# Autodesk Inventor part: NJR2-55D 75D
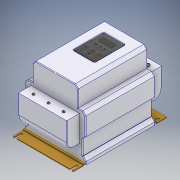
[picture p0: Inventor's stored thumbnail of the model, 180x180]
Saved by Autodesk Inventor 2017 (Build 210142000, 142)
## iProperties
Part Number: NJR2-55D 75D
Material: Типовые
Document SubType Name: Modeling
Designer: RSagdiev
Density: 1 g/cm^3
Appearance: По умолчанию
Author: RSagdiev
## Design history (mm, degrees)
sketch "Эскиз1"
  geometry: L1 (0, 0)-(14.471, 0) reference; L2 (0, 0)-(0, 21.118) reference; L3 (0, 0)-(230, 0); L4 (230, 0)-(230, 20); L5 (230, 215)-(0, 215); L6 (0, 215)-(0, 150); L7 (230, 20)-(0, 20); L8 (230, 70)-(0, 70); L9 (230, 70)-(230, 150); L10 (230, 20)-(230, 70); L11 (0, 70)-(0, 20); L12 (0, 20)-(0, 0); L13 (230, 150)-(0, 150); L14 (230, 150)-(230, 215); L15 (0, 150)-(0, 70)
  constraints: 30 end point, 17 parallel, 14 perpendicular, 3 horizontal, 2 vertical, 1 point on line
  dimensions: "d0" = 230 distance of L5.end L5.start; "d1" = 215 distance of L5.start L3.end; "d2" = 20 distance between parallel lines of L3 L7; "d3" = 50 distance between parallel lines of L8 L7; "d4" = 80 distance between parallel lines of L13 L8
extrude "Выдавливание1" new body sketch "Эскиз1" stored distance "d5" = 202; taper "d6" = 0 deg
extrude "Выдавливание2" join sketch "Эскиз1" stored distance "d7" = 180; taper "d8" = 0 deg
extrude "Выдавливание3" join sketch "Эскиз1" stored distance "d9" = 200; taper "d10" = 0 deg
extrude "Выдавливание4" join sketch "Эскиз1" stored distance "d11" = 150; taper "d12" = 0 deg
chamfer "Фаска1" distance "d13" = 10; stored, may be unused: second distance "d14" = 2, angle "d15" = 45 deg
sketch "Эскиз2"
  geometry: L1 (270, 0)-(236, 0); L2 (235, 1)-(235, 3); L3 (234, 4)-(-4, 4); L4 (-5, 3)-(-5, 1); L5 (-6, 0)-(-40, 0); L6 (230, 10)-(230, 0) reference; L7 (230, 0)-(0, 0) reference; L8 (0, 0)-(0, 10) reference; L9 (270, 3)-(238, 3); L10 (234, 7)-(-4, 7); L11 (-8, 3)-(-40, 3); L12 (-40, 0)-(-40, 3); L13 (270, 3)-(270, 0); A1 r 1 centre (-6, 1) between (-6, 0) and (-5, 1); A2 r 1 centre (-4, 3) between (-4, 4) and (-5, 3); A3 r 1 centre (236, 1) between (235, 1) and (236, 0); A4 r 1 centre (234, 3) between (235, 3) and (234, 4); A5 r 4 centre (234, 3) between (238, 3) and (234, 7); A6 r 4 centre (-4, 3) between (-4, 7) and (-8, 3); 4 further points
  constraints: 20 end point, 12 point on circle, 10 point on line, 8 tangent, 6 centre point, 4 perpendicular, 3 equal radius, 1 horizontal, 1 parallel, 4 other
  dimensions: "d16" = 4 distance of point (235, 0) point (235, 4); "d17" = 5 distance between parallel lines of L2 L6; "d18" = 4 distance between parallel lines of L7 L3; "d19" = 35 distance of point (235, 0) L1.start; "d20" = 35 distance of point (-5, 0) L5.end (= d19); "d21" = 4 distance of point (-5, 4) point (-5, 0) (derived); "d22" = 5 distance between parallel lines of L4 L8 (= d17); "d23" = 310 distance of L5.end L1.start (derived); "d24" = 1 radius of A1; "d25" = 3 distance between parallel lines of L1 L9
extrude "Выдавливание5" new body sketch "Эскиз2" stored distance "d26" = 200; taper "d27" = 0 deg
sketch "Эскиз4"
  geometry: L1 (272.5, 138)-(-42.5, 138); L2 (-42.5, 138)-(-42.5, 50); L3 (-42.5, 50)-(272.5, 50); L4 (272.5, 50)-(272.5, 138); L5 (230, 150)-(230, 205) reference; L6 (230, 150)-(0, 150) reference; L7 (230, 70)-(0, 70) reference; 1 further point
  constraints: 8 end point, 2 parallel, 1 horizontal, 1 perpendicular
  dimensions: "d28" = 315 distance between parallel lines of L2 L4; "d29" = 42.5 distance between parallel lines of L4 L5 (= -0.5 x d0 + 0.5 x d28); "d31" = 20 distance between parallel lines of L7 L3; "d34" = 12 distance between parallel lines of L1 L6
extrude "Выдавливание6" join sketch "Эскиз4" stored distance "d32" = 160; taper "d33" = 0 deg
fillet "Сопряжение1" dims "d35" = 25
sketch "Эскиз5" dims "d44" = 10
  geometry: L1 (160, 0)-(0, 0) reference; L2 (160, 42.5)-(160, 0) reference; L3 (160, 42.5)-(0, 42.5) reference; L4 (0, 0)-(0, 42.5) reference; C1 r 4 at (20, 20); C2 r 4 at (43.333, 20); C3 r 4 at (66.667, 20); C4 r 4 at (90, 20); C5 r 4 at (113.333, 20); C6 r 4 at (136.667, 20); 1 further point
  constraints: 6 centre point, 1 horizontal, 10 other
  dimensions: "d36" = 8 diameter of C1; "d37" = 160 distance between parallel lines of L2 L4 (derived); "d38" = 20 distance from line of C1.centre L4; "d41" = 23.33333 distance of C1.centre C2.centre (= -0.166667 x d38 + 0.166667 x d37)
  node "Спроецированная петля1"
extrude "Выдавливание7" cut sketch "Эскиз5" distance "d46" = 20; taper "d47" = 0 deg
extrude "Выдавливание8" new body sketch "Эскиз5" distance "d48" = 20; taper "d49" = 0 deg
sketch "Эскиз6" dims "d50" = 12, "d56" = 10
  geometry: L1 (0, 6)-(5.196, 3); L2 (5.196, 3)-(5.196, -3); L3 (5.196, -3)-(0, -6); L4 (0, -6)-(-5.196, -3); L5 (-5.196, -3)-(-5.196, 3); L6 (-5.196, 3)-(0, 6); L7 (140, 22.5)-(-20, 22.5) reference; L8 (23.333, 6)-(28.529, 3); L9 (28.529, 3)-(28.529, -3); L10 (28.529, -3)-(23.333, -6); L11 (23.333, -6)-(18.137, -3); L12 (18.137, -3)-(18.137, 3); L13 (18.137, 3)-(23.333, 6); L14 (46.667, 6)-(51.863, 3); L15 (51.863, 3)-(51.863, -3); L16 (51.863, -3)-(46.667, -6); L17 (46.667, -6)-(41.471, -3); L18 (41.471, -3)-(41.471, 3); L19 (41.471, 3)-(46.667, 6); L20 (70, 6)-(75.196, 3); L21 (75.196, 3)-(75.196, -3); L22 (75.196, -3)-(70, -6); L23 (70, -6)-(64.804, -3); L24 (64.804, -3)-(64.804, 3); L25 (64.804, 3)-(70, 6); L26 (93.333, 6)-(98.529, 3); L27 (98.529, 3)-(98.529, -3); L28 (98.529, -3)-(93.333, -6); L29 (93.333, -6)-(88.137, -3); L30 (88.137, -3)-(88.137, 3); L31 (88.137, 3)-(93.333, 6); L32 (116.667, 6)-(121.863, 3); L33 (121.863, 3)-(121.863, -3); L34 (121.863, -3)-(116.667, -6); L35 (116.667, -6)-(111.471, -3); L36 (111.471, -3)-(111.471, 3); L37 (111.471, 3)-(116.667, 6); 13 further points
  constraints: 72 end point, 6 coincident, 6 horizontal, 6 vertical alignment, 95 other
  dimensions: "d53" = 23.33333 distance of point (0, 0) point (23.333, 0) (= -0.166667 x d38 + 0.166667 x d37)
extrude "Выдавливание9" join sketch "Эскиз6" distance "d58" = 5; taper "d59" = 0 deg
sketch "Эскиз7"
  geometry: L1 (5.196, 3)-(0, 6) reference; L2 (0, 6)-(-5.196, 3) reference; L3 (-5.196, 3)-(-5.196, -3) reference; L4 (-5.196, -3)-(0, -6) reference; L5 (0, -6)-(5.196, -3) reference; L6 (5.196, -3)-(5.196, 3) reference; L7 (0, 3.691)-(3.196, 1.845); L8 (3.196, 1.845)-(3.196, -1.845); L9 (3.196, -1.845)-(0, -3.691); L10 (0, -3.691)-(-3.196, -1.845); L11 (-3.196, -1.845)-(-3.196, 1.845); L12 (-3.196, 1.845)-(0, 3.691); L13 (28.529, 3)-(23.333, 6) reference; L14 (23.333, 6)-(18.137, 3) reference; L15 (18.137, 3)-(18.137, -3) reference; L16 (18.137, -3)-(23.333, -6) reference; L17 (23.333, -6)-(28.529, -3) reference; L18 (28.529, -3)-(28.529, 3) reference; L19 (51.863, 3)-(46.667, 6) reference; L20 (46.667, 6)-(41.471, 3) reference; L21 (41.471, 3)-(41.471, -3) reference; L22 (41.471, -3)-(46.667, -6) reference; L23 (46.667, -6)-(51.863, -3) reference; L24 (51.863, -3)-(51.863, 3) reference; L25 (75.196, 3)-(70, 6) reference; L26 (70, 6)-(64.804, 3) reference; L27 (64.804, 3)-(64.804, -3) reference; L28 (64.804, -3)-(70, -6) reference; L29 (70, -6)-(75.196, -3) reference; L30 (75.196, -3)-(75.196, 3) reference; L31 (98.529, 3)-(93.333, 6) reference; L32 (93.333, 6)-(88.137, 3) reference; L33 (88.137, 3)-(88.137, -3) reference; L34 (88.137, -3)-(93.333, -6) reference; L35 (93.333, -6)-(98.529, -3) reference; L36 (98.529, -3)-(98.529, 3) reference; L37 (121.863, 3)-(116.667, 6) reference; L38 (116.667, 6)-(111.471, 3) reference; L39 (111.471, 3)-(111.471, -3) reference; L40 (111.471, -3)-(116.667, -6) reference; L41 (116.667, -6)-(121.863, -3) reference; L42 (121.863, -3)-(121.863, 3) reference; L43 (23.333, 3.691)-(26.529, 1.845); L44 (26.529, 1.845)-(26.529, -1.845); L45 (26.529, -1.845)-(23.333, -3.691); L46 (23.333, -3.691)-(20.137, -1.845); L47 (20.137, -1.845)-(20.137, 1.845); L48 (20.137, 1.845)-(23.333, 3.691); L49 (43.471, 1.845)-(46.667, 3.691); L50 (46.667, 3.691)-(49.863, 1.845); L51 (49.863, 1.845)-(49.863, -1.845); L52 (49.863, -1.845)-(46.667, -3.691); L53 (46.667, -3.691)-(43.471, -1.845); L54 (43.471, -1.845)-(43.471, 1.845); L55 (66.804, 1.845)-(70, 3.691); L56 (70, 3.691)-(73.196, 1.845); L57 (73.196, 1.845)-(73.196, -1.845); L58 (73.196, -1.845)-(70, -3.691); L59 (70, -3.691)-(66.804, -1.845); L60 (66.804, -1.845)-(66.804, 1.845); L61 (90.137, 1.845)-(93.333, 3.691); L62 (93.333, 3.691)-(96.529, 1.845); L63 (96.529, 1.845)-(96.529, -1.845); L64 (96.529, -1.845)-(93.333, -3.691)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; 1 further point
  constraints: 72 end point, 30 other
  dimensions: "d60" = 2 distance between parallel lines of L1 L7; "d61" = 2 distance between parallel lines of L13 L43; "d62" = 2 distance between parallel lines of L20 L49; "d63" = 2 distance between parallel lines of L26 L55; "d64" = 2 distance between parallel lines of L32 L61; "d65" = 2 distance between parallel lines of L38 L67
extrude "Выдавливание10" cut sketch "Эскиз7" distance "d66" = 1.5; taper "d67" = 0 deg
fillet "Сопряжение2" dims "d68" = 2
sketch "Эскиз8"
  geometry: L1 (0, -310)-(200, -310) reference; L2 (200, 0)-(0, 0) reference; L3 (200, 0)-(200, -34) reference; L4 (0, -34)-(0, 0) reference; L5 (8.5, -20)-(8.5, -25); L6 (191.5, -20)-(191.5, -25); L7 (8.5, -20)-(191.5, -20); L8 (8.5, -290)-(8.5, -310); L9 (5, -290)-(5, -310); L10 (12, -310)-(12, -290); L11 (8.5, -20)-(8.5, -290); L12 (8.5, -290)-(191.5, -290); L13 (191.5, -20)-(191.5, -290); L14 (191.5, -290)-(191.5, -310); L15 (188, -290)-(188, -310); L16 (195, -310)-(195, -290); A1 r 3.5 centre (8.5, -20) between (11.779, -21.225) and (5.221, -21.225); A2 r 5 centre (8.5, -25) between (5.221, -21.225) and (11.779, -21.225); A3 r 3.5 centre (191.5, -20) between (194.779, -21.225) and (188.221, -21.225); A4 r 5 centre (191.5, -25) between (188.221, -21.225) and (194.779, -21.225); A5 r 3.5 centre (8.5, -290) between (12, -290) and (5, -290); A6 r 3.5 centre (8.5, -310) between (5, -310) and (12, -310); A7 r 3.5 centre (191.5, -290) between (195, -290) and (188, -290); A8 r 3.5 centre (191.5, -310) between (188, -310) and (195, -310); 5 further points
  constraints: 28 end point, 16 point on circle, 8 centre point, 8 tangent, 4 vertical, 3 coincident, 2 horizontal, 2 midpoint, 2 parallel, 2 perpendicular, 2 point on line
  dimensions: "d69" = 183 distance of point (191.5, -20) point (8.5, -20); "d70" = 270 distance of L8.start point (8.5, -20); "d71" = 310 distance between parallel lines of L1 L2 (derived); "d72" = 20 distance from line of L2 point (8.5, -20) (= -0.5 x d70 + 0.5 x d71); "d73" = 200 distance between parallel lines of L3 L4 (derived); "d74" = 8.5 distance from line of L4 point (8.5, -20) (= -0.5 x d69 + 0.5 x d73); "d75" = 7 diameter of A1; "d76" = 10 diameter of A2; "d77" = 5 distance of L5.start L5.end; "d78" = 7 diameter of A3; "d79" = 10 diameter of A4; "d80" = 5 distance of L6.start L6.end; "d81" = 7 diameter of A6; "d82" = 7 diameter of A8
extrude "Выдавливание11" cut sketch "Эскиз8" distance "d83" = 5.5; taper "d84" = 0 deg
fillet "Сопряжение3" dims "d85" = 2
sketch "Эскиз9"
  geometry: L1 (130, 0)-(0, 0) reference; L2 (130, 226)-(130, 0) reference; L3 (0, 226)-(130, 226) reference; L4 (0, 0)-(0, 226) reference; L5 (33, 193)-(97, 193); L6 (100, 190)-(100, 96); L7 (97, 93)-(33, 93); L8 (30, 96)-(30, 190); L9 (97, 195)-(33, 195); L10 (28, 190)-(28, 96); L11 (33, 91)-(97, 91); L12 (102, 96)-(102, 190); A1 r 3 centre (33, 190) between (33, 193) and (30, 190); A2 r 3 centre (97, 190) between (100, 190) and (97, 193); A3 r 3 centre (97, 96) between (97, 93) and (100, 96); A4 r 3 centre (33, 96) between (30, 96) and (33, 93); A5 r 5 centre (33, 190) between (33, 195) and (28, 190); A6 r 5 centre (33, 96) between (28, 96) and (33, 91); A7 r 5 centre (97, 96) between (97, 91) and (102, 96); A8 r 5 centre (97, 190) between (102, 190) and (97, 195); 4 further points
  constraints: 16 end point, 16 point on circle, 8 centre point, 8 tangent, 6 point on line, 4 parallel, 3 equal radius, 2 perpendicular, 1 horizontal, 7 other
  dimensions: "d86" = 70 distance of point (100, 93) point (30, 93); "d87" = 100 distance of point (100, 193) point (100, 93); "d88" = 130 distance of L3.start L2.start (derived); "d89" = 226 distance of L1.end L3.start (derived); "d90" = 33 distance between parallel lines of L3 L5 (computed from d89, d87); "d91" = 30 distance between parallel lines of L4 L8 (= -0.5 x d86 + 0.5 x d88); "d92" = 3 radius of A1; "d93" = 2 distance between parallel lines of L5 L9
  node "Спроецированная петля8"
extrude "Выдавливание12" cut sketch "Эскиз9" distance "d94" = 25; taper "d95" = 0 deg
extrude "Выдавливание13" new body sketch "Эскиз9" distance "d96" = 25; taper "d97" = 0 deg
sketch "Эскиз10"
  geometry: L1 (30, 190)-(30, 150.574); L2 (33, 93)-(97, 93); L3 (100, 96)-(100, 150.574); L4 (97, 193)-(33, 193); L5 (97, 193)-(33, 193) reference; L6 (30, 190)-(30, 96) reference; L7 (30, 150.574)-(30, 96); L8 (100, 150.574)-(100, 190); L9 (45.628, 161.287)-(84.628, 161.287); L10 (87.628, 164.287)-(87.628, 176.287); L11 (84.628, 179.287)-(45.628, 179.287); L12 (42.628, 176.287)-(42.628, 164.287); L13 (42.628, 161.287)-(87.628, 179.287); L14 (87.628, 161.287)-(42.628, 179.287); A1 r 3 centre (33, 96) between (30, 96) and (33, 93); A2 r 3 centre (97, 96) between (97, 93) and (100, 96); A3 r 3 centre (97, 190) between (100, 190) and (97, 193); A4 r 3 centre (33, 190) between (33, 193) and (30, 190); A5 r 55 centre (65, 193) between (30, 150.574) and (100.197, 150.737); A6 r 3 centre (45.628, 176.287) between (45.628, 179.287) and (42.628, 176.287); A7 r 3 centre (45.628, 164.287) between (42.628, 164.287) and (45.628, 161.287); A8 r 3 centre (84.628, 176.287) between (87.628, 176.287) and (84.628, 179.287); A9 r 3 centre (84.628, 164.287) between (84.628, 161.287) and (87.628, 164.287); 2 further points
  constraints: 20 end point, 11 point on circle, 9 centre point, 9 point on line, 8 tangent, 3 equal radius, 3 midpoint, 2 parallel, 1 horizontal, 1 perpendicular
  dimensions: "d98" = 55 radius of A5; "d99" = 45 distance of L14.end L13.end; "d100" = 18 distance of L13.end L14.start; "d101" = 22.7132 distance from line of L4 point (65.128, 170.287); "d102" = 35.1281 distance from line of L1 point (65.128, 170.287); "d103" = 3 radius of A6 (derived)
extrude "Выдавливание14" cut sketch "Эскиз10" distance "d104" = 1; taper "d105" = 0 deg
sketch "Эскиз11"
  geometry: L1 (30, 150.574)-(30, 96) reference; L2 (33, 93)-(97, 93) reference; L3 (100, 96)-(100, 150.574) reference; L4 (30, 150.574)-(30, 96) reference; L5 (30, 123)-(100, 123); L6 (100, 96)-(100, 150.574) reference; L7 (30, 108)-(100, 108); L8 (33, 93)-(97, 93) reference; L9 (41.667, 93)-(41.667, 143.195); L10 (88.333, 93)-(88.333, 143.195); L11 (65, 93)-(65, 138); L12 (36.667, 128)-(46.667, 128); L13 (46.667, 128)-(46.667, 118); L14 (46.667, 118)-(36.667, 118); L15 (36.667, 118)-(36.667, 128); L16 (36.667, 128)-(46.667, 118); L17 (46.667, 128)-(36.667, 118); L18 (36.667, 113)-(46.667, 113); L19 (46.667, 113)-(46.667, 103); L20 (46.667, 103)-(36.667, 103); L21 (36.667, 103)-(36.667, 113); L22 (36.667, 113)-(46.667, 103); L23 (46.667, 113)-(36.667, 103); L24 (60, 128)-(70, 128); L25 (70, 128)-(70, 118); L26 (70, 118)-(60, 118); L27 (60, 118)-(60, 128); L28 (60, 128)-(70, 118); L29 (70, 128)-(60, 118); L30 (60, 113)-(70, 113); L31 (70, 113)-(70, 103); L32 (70, 103)-(60, 103); L33 (60, 103)-(60, 113); L34 (60, 113)-(70, 103); L35 (70, 113)-(60, 103); L36 (83.333, 128)-(93.333, 128); L37 (93.333, 128)-(93.333, 118); L38 (93.333, 118)-(83.333, 118); L39 (83.333, 118)-(83.333, 128); L40 (83.333, 128)-(93.333, 118); L41 (93.333, 128)-(83.333, 118); L42 (83.333, 113)-(93.333, 113); L43 (93.333, 113)-(93.333, 103); L44 (93.333, 103)-(83.333, 103); L45 (83.333, 103)-(83.333, 113); L46 (83.333, 113)-(93.333, 103); L47 (93.333, 113)-(83.333, 103); L48 (46.767, 128.1)-(36.567, 128.1); L49 (36.567, 128.1)-(36.567, 117.9); L50 (36.567, 117.9)-(46.767, 117.9); L51 (46.767, 117.9)-(46.767, 128.1); L52 (70.1, 128.1)-(59.9, 128.1); L53 (59.9, 128.1)-(59.9, 117.9); L54 (59.9, 117.9)-(70.1, 117.9); L55 (70.1, 117.9)-(70.1, 128.1); L56 (93.433, 128.1)-(83.233, 128.1); L57 (83.233, 128.1)-(83.233, 117.9); L58 (83.233, 117.9)-(93.433, 117.9); L59 (93.433, 117.9)-(93.433, 128.1); L60 (46.767, 113.1)-(36.567, 113.1); L61 (36.567, 113.1)-(36.567, 102.9); L62 (36.567, 102.9)-(46.767, 102.9); L63 (46.767, 102.9)-(46.767, 113.1); L64 (70.1, 113.1)-(59.9, 113.1)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; A1 r 55 centre (65, 193) between (30, 150.574) and (100, 150.574) reference; A2 r 3 centre (33, 96) between (30, 96) and (33, 93) reference; A3 r 3 centre (97, 96) between (97, 93) and (100, 96) reference; A4 r 55 centre (65, 193) between (30, 150.574) and (100, 150.574) reference; 8 further points
  constraints: 130 end point, 24 parallel, 16 midpoint, 16 point on line, 14 perpendicular, 7 horizontal, 4 point on circle, 1 vertical, 18 other
  dimensions: "d106" = 70 distance between parallel lines of L3 L1 (derived); "d107" = 45 distance from line of L2 L11.end (derived); "d108" = 15 distance between parallel lines of L7 L5 (= 0.333333 x d107); "d109" = 15 distance from line of L11.end L5 (= 0.333333 x d107); "d110" = 23.33333 distance between parallel lines of L11 L10 (= 0.333333 x d106); "d111" = 23.33333 distance between parallel lines of L11 L9 (= d110); "d112" = 10 distance of L13.end L14.end; "d113" = 10 distance of L12.end L13.end; "d114" = 10 distance of L19.end L20.end; "d115" = 10 distance of L18.end L19.end; "d116" = 10 distance of L25.end L26.end; "d117" = 10 distance of L24.end L25.end; "d118" = 10 distance of L31.end L32.end; "d119" = 10 distance of L30.end L31.end; "d120" = 10 distance of L37.end L38.end; "d121" = 10 distance of L36.end L37.end; "d122" = 10 distance of L43.end L44.end; "d123" = 10 distance of L42.end L43.end; "d124" = 0.1 distance between parallel lines of L12 L48; "d125" = 0.1 distance between parallel lines of L24 L52; "d126" = 0.1 distance between parallel lines of L36 L56; "d127" = 0.1 distance between parallel lines of L18 L60; "d128" = 0.1 distance between parallel lines of L30 L64; "d129" = 0.1 distance between parallel lines of L42 L68
extrude "Выдавливание15" cut sketch "Эскиз11" distance "d130" = 3; taper "d131" = 0 deg
sketch "Эскиз12"
  geometry: L1 (100, 96)-(100, 150.574) reference; L2 (50, 144.701)-(80, 144.701); C1 r 1.5 at (65, 144.701); C2 r 1.5 at (80, 144.701); C3 r 1.5 at (50, 144.701); C4 r 1.6 at (50, 144.701); C5 r 1.6 at (65, 144.701); C6 r 1.6 at (80, 144.701); A1 r 55 centre (65, 193) between (30, 150.574) and (100, 150.574) reference; 1 further point
  constraints: 6 centre point, 2 end point, 1 coincident, 1 horizontal, 1 midpoint
  dimensions: "d132" = 3 diameter of C1; "d133" = 3 diameter of C2; "d134" = 3 diameter of C3; "d135" = 48.29941 distance of A1.centre C1.centre; "d136" = 35 distance from line of L1 C1.centre; "d137" = 15 distance of C1.centre C2.centre; "d138" = 15 distance of C1.centre L2.start; "d139" = 0.1 radial gap between concentric circles of C3 C4; "d140" = 0.1 radial gap between concentric circles of C1 C5; "d141" = 0.1 radial gap between concentric circles of C2 C6
extrude "Выдавливание16" cut sketch "Эскиз12" distance "d142" = 3; taper "d143" = 0 deg
sketch "Эскиз13"
  geometry: L1 (45, 150.348)-(102.075, 150.348); L2 (102.075, 150.348)-(102.075, 146.701); L3 (102.075, 146.701)-(45, 146.701); L4 (45, 146.701)-(45, 150.348); C1 r 1.5 at (50, 144.701) reference; 1 further point
  constraints: 2 other
  dimensions: "d144" = 2 vertical distance of L3.end C1.centre; "d145" = 5 horizontal distance of C1.centre L3.end
feature "Рельеф1" sketch "Эскиз13" dims "d146" = 0.1, "d147" = 0
sketch "Эскиз14"
  geometry: L1 (36.734, 124.406)-(51.145, 124.406); L2 (51.145, 124.406)-(51.145, 120.906); L3 (51.145, 120.906)-(36.734, 120.906); L4 (36.734, 120.906)-(36.734, 124.406); L5 (38.873, 106.059)-(38.873, 109.559); L6 (38.873, 109.559)-(53.285, 109.559); L7 (53.285, 109.559)-(53.285, 106.059); L8 (53.285, 106.059)-(38.873, 106.059); L9 (84.699, 105.985)-(84.699, 109.485); L10 (84.699, 109.485)-(99.11, 109.485); L11 (99.11, 109.485)-(99.11, 105.985); L12 (99.11, 105.985)-(84.699, 105.985); L13 (85.21, 120.906)-(85.21, 124.406); L14 (85.21, 124.406)-(99.621, 124.406); L15 (99.621, 124.406)-(99.621, 120.906); L16 (99.621, 120.906)-(85.21, 120.906); 1 further point
  constraints: 8 other
feature "Рельеф2" dims "d148" = 0.1, "d149" = 0
feature "Рельеф3" dims "d150" = 0.1, "d151" = 0
feature "Рельеф4" dims "d152" = 0.1, "d153" = 0
feature "Рельеф5" dims "d154" = 0.1, "d155" = 0
sketch "Эскиз15" dims "d156" = 6, "d157" = 6
  geometry: L1 (60, 128)-(60, 118) reference; L2 (60, 118)-(70, 118) reference; L3 (70, 118)-(70, 128) reference; L4 (70, 128)-(60, 128) reference; L5 (60, 113)-(60, 103) reference; L6 (60, 103)-(70, 103) reference; L7 (70, 103)-(70, 113) reference; L8 (70, 113)-(60, 113) reference; L9 (60, 118)-(70, 128); L10 (60, 128)-(70, 118); L11 (60, 113)-(70, 103); L12 (70.1, 113.1)-(70.1, 102.9) reference; L13 (70.1, 113.1)-(60, 103); L14 (65.05, 126)-(67.573, 121.457); L15 (67.573, 121.457)-(62.377, 121.544); L16 (62.377, 121.544)-(65.05, 126); L17 (65.05, 105.05)-(62.452, 109.55); L18 (62.452, 109.55)-(67.648, 109.55); L19 (67.648, 109.55)-(65.05, 105.05); 5 further points
  constraints: 20 end point, 2 coincident, 2 midpoint, 2 perpendicular, 1 parallel, 1 vertical alignment, 19 other
  node "Спроецированная петля11"
  node "Спроецированная петля12"
feature "Рельеф6" dims "d158" = 0.1, "d159" = 0
feature "Рельеф7" dims "d160" = 0.1, "d161" = 0
sketch "Эскиз16"
  geometry: L1 (2, -42.5)-(158, -42.5) reference; L2 (160, 0)-(160, -40.5) reference; L3 (0, 0)-(160, 0) reference; L4 (0, -40.5)-(0, 0) reference; L5 (130, -22.5)-(0, -22.5); L6 (0, -40.5)-(0, -17.5) reference; C1 r 4 at (30, -22.5); C2 r 4 at (80, -22.5); C3 r 4 at (130, -22.5); A1 r 2 centre (2, -40.5) between (0, -40.5) and (2, -42.5) reference; A2 r 2 centre (158, -40.5) between (158, -42.5) and (160, -40.5) reference; 1 further point
  constraints: 3 centre point, 3 point on line, 2 end point, 1 horizontal
  dimensions: "d162" = 8 diameter of C1; "d163" = 8 diameter of C2; "d164" = 8 diameter of C3; "d165" = 30 distance from line of L2 L5.start; "d166" = 20 distance from line of L5.start L1; "d167" = 50 distance of C2.centre L5.start; "d168" = 50 distance of C1.centre C2.centre
extrude "Выдавливание17" new body sketch "Эскиз16" distance "d169" = 3; taper "d170" = 0 deg
sketch "Эскиз17"
  geometry: L1 (-28, -20)-(128, -20) reference; L2 (130, 22.5)-(130, -18) reference; L3 (-30, 22.5)-(130, 22.5) reference; L4 (-30, -18)-(-30, 22.5) reference; L5 (0, 3)-(2.598, 1.5); L6 (2.598, 1.5)-(2.598, -1.5); L7 (2.598, -1.5)-(0, -3); L8 (0, -3)-(-2.598, -1.5); L9 (-2.598, -1.5)-(-2.598, 1.5); L10 (-2.598, 1.5)-(0, 3); L11 (50, 3)-(52.598, 1.5); L12 (52.598, 1.5)-(52.598, -1.5); L13 (52.598, -1.5)-(50, -3); L14 (50, -3)-(47.402, -1.5); L15 (47.402, -1.5)-(47.402, 1.5); L16 (47.402, 1.5)-(50, 3); L17 (100, 3)-(102.598, 1.5); L18 (102.598, 1.5)-(102.598, -1.5); L19 (102.598, -1.5)-(100, -3); L20 (100, -3)-(97.402, -1.5); L21 (97.402, -1.5)-(97.402, 1.5); L22 (97.402, 1.5)-(100, 3); C1 r 4 at (0, 0) reference; C2 r 4 at (50, 0) reference; C3 r 4 at (100, 0) reference; C4 r 4 at (50, 0) reference; A1 r 2 centre (-28, -18) between (-30, -18) and (-28, -20) reference; A2 r 2 centre (128, -18) between (128, -20) and (130, -18) reference; 4 further points
  constraints: 36 end point, 3 coincident, 3 vertical alignment, 45 other
  dimensions: "d171" = 1 dimension on C1; "d172" = 1 dimension on C2; "d173" = 1 dimension on C3
extrude "Выдавливание18" cut sketch "Эскиз17" distance "d174" = 0.5; taper "d175" = 0 deg
fillet "Сопряжение4" dims "d176" = 1
node "Твердое тело1"
node "Твердое тело2"
node "Твердое тело3"
node "Спроецированная петля2"
node "Спроецированная петля3"
node "Спроецированная петля4"
node "Спроецированная петля5"
node "Спроецированная петля6"
node "Спроецированная петля7"
node "Твердое тело4"
node "Спроецированная петля10"
node "Спроецированная петля13"
node "Твердое тело5"
node "Спроецированная петля14"
node "Спроецированная петля15"
node "Спроецированная петля16"
node "Спроецированная петля17"
